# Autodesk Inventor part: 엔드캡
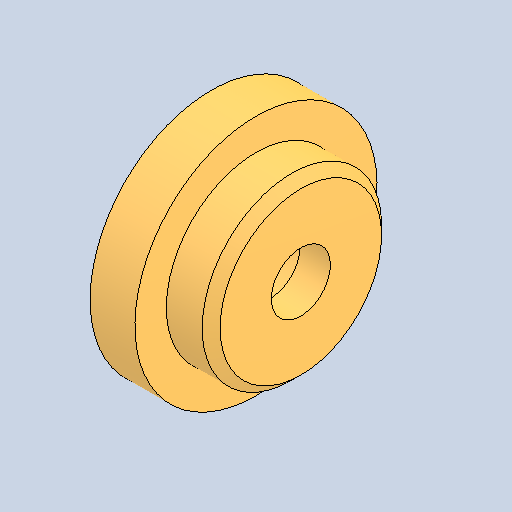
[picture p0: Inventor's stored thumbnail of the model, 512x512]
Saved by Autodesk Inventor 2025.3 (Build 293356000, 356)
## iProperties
Created: 2026-01
Part Number: 엔드캡
Material: 강철, 연강
Document SubType Name: Modeling
Designer: pc6
Density: 7.85 g/cm^3
Appearance: 기본값
Author: jhkim
Sending System: Autodesk Inventor 2026
Preprocessor: ST-DEVELOPER v20.1
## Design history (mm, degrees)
feature "솔리드1"
node "솔리드2"
